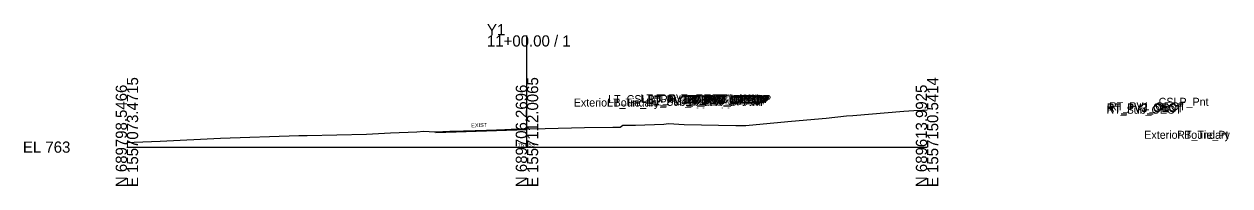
# Model space of a CAD drawing. Extents: x -26 to 303, y -10 to 5005.
# Drawn here: x -25.7 to 275.7, y 990.3 to 1030.7 of the extents above; entities that cross this region are included whole.
import ezdxf

# ---------------------------------------------------------------- set-up
doc = ezdxf.new("R2010")
doc.units = 0
for name, color, linetype in [('Default', 7, 'Continuous'), ('Exist Cross Section Cell', 7, 'Continuous'), ('Exist XS Center Line Elevation Label', 7, 'Continuous'), ('Exist XS Ground Line', 7, 'Continuous'), ('Prop CMT Pvmt Course 1', 7, 'Continuous'), ('Prop CMT Pvmt Surface', 7, 'Continuous'), ('Prop XS SE Text', 7, 'Continuous')]:
    doc.layers.add(name, color=color, linetype=linetype)

msp = doc.modelspace()

# ---------------------------------------------------------------- linework, layer by layer
at = {"layer": 'Exist Cross Section Cell'}
for p, q in [((100, 1000), (100, 1027.94)), ((0, 1000), (100, 1000)), ((100, 1000), (200, 1000))]:
    msp.add_line(p, q, dxfattribs=at)
at = {"layer": 'Exist XS Ground Line'}
msp.add_lwpolyline([(0, 1001.18), (1.79, 1001.23), (8.29, 1001.45), (23.36, 1002.24), (42.94, 1002.87), (44.41, 1002.89), (45.02, 1002.9), (59.93, 1003.22), (65.9, 1003.55), (72.5, 1003.85), (74.21, 1003.98), (76.87, 1003.83), (77.22, 1003.8), (80.71, 1004), (81.25, 1004.02), (92.77, 1004.36), (96.07, 1004.45), (100, 1004.55), (104.53, 1004.67), (114.37, 1004.86), (121.45, 1005.01), (122.06, 1005.01), (123.31, 1005.02), (123.95, 1005.48), (127.14, 1005.51), (134.18, 1005.75), (135.41, 1005.87), (139.33, 1005.62), (152.24, 1005.4), (154.67, 1005.39), (157.29, 1005.67), (166.13, 1006.45), (174.76, 1007.24), (179.85, 1007.83), (181.43, 1007.93), (194.2, 1008.98), (196.68, 1009.17), (198.84, 1009.27), (200, 1009.31)], dxfattribs=at)
at = {"layer": 'Prop CMT Pvmt Course 1'}
for p, q in [((77.22, 1003.68), (100, 1004.42)), ((77.22, 1003.8), (77.22, 1003.68))]:
    msp.add_line(p, q, dxfattribs=at)
for points in [[(100, 1004.55), (100, 1004.42)], [(100, 1004.42), (100, 1004.55)]]:
    msp.add_lwpolyline(points, dxfattribs=at)
at = {"layer": 'Prop CMT Pvmt Surface'}
msp.add_line((77.22, 1003.8), (100, 1004.55), dxfattribs=at)

# ---------------------------------------------------------------- texts
at = {"layer": 'Default'}
for s, height, p in [('LT_CSLP_Pnt', 2, (120.3, 1010.99)), ('LT_CG_Top_BOC', 2, (128.4, 1011.19)), ('LT_PV2_OEOT', 2, (130.29, 1010.94)), ('LT_PV3_OEOT', 2, (130.29, 1010.69)), ('LT_PV1_OEOT', 2, (130.86, 1011.19)), ('RT_PV2_OEEOP', 2, (139.37, 1010.92)), ('RT_PV3_OEEOP', 2, (139.37, 1010.67)), ('LT_PV2_OEEOP', 2, (139.42, 1010.92)), ('LT_PV3_OEEOP', 2, (139.42, 1010.67)), ('RT_PV1_OEEOP', 2, (139.94, 1011.04)), ('LT_PV1_OEEOP', 2, (139.98, 1011.04)), ('RT_PV2_IEEOP', 2, (140.01, 1010.92)), ('LT_PV2_IEEOP', 2, (140.06, 1010.92)), ('RT_PV1_IEEOP', 2, (140.58, 1011.04)), ('LT_PV1_IEEOP', 2, (140.63, 1011.04)), ('RT_PV2_PGL', 2, (141.27, 1010.92)), ('LT_PV2_PGL', 2, (141.32, 1010.92)), ('RT_PV1_PGL', 2, (141.84, 1011.17)), ('LT_PV1_PGL', 2, (141.89, 1011.17)), ('Exterior Boundary', 2, (111.7, 1010.14)), ('LT_Tie_Pt', 2, (120, 1010.14)), ('LT_Sub_OEOT', 2, (130.2, 1010.32)), ('RT_Sub_OEEOP', 2, (139.27, 1010.29)), ('LT_Sub_OEEOP', 2, (139.32, 1010.29)), ('RT_Sub_OEOT', 2, (244.83, 1008.34)), ('RT_PV2_OEOT', 2, (244.93, 1008.96)), ('RT_PV3_OEOT', 2, (244.93, 1008.71)), ('RT_PV1_OEOT', 2, (245.49, 1009.21)), ('CSLP_Pnt', 2, (257.89, 1010.33)), ('Exterior Boundary', 2, (254.3, 1002.07)), ('RT_Tie_Pt', 2, (262.55, 1002.07)), ('-', 0.0001, (0, 1000))]:
    msp.add_text(s, height=height, dxfattribs=at).set_placement(p)
at = {"layer": 'Exist Cross Section Cell'}
for s, p in [('Y1', (90, 1027.94)), ('11+00.00 / 1', (90, 1025.14)), ('EL 763', (-26, 998.6))]:
    msp.add_text(s, height=2.8, dxfattribs=at).set_placement(p)
for s, p in [('E 1557073.4715', (2.8, 990)), ('E 1557112.0065', (102.8, 990)), ('E 1557150.5414', (202.8, 990)), ('N 689798.5466', (0, 990)), ('N 689706.2696', (100, 990)), ('N 689613.9925', (200, 990))]:
    msp.add_text(s, height=2.8, rotation=90, dxfattribs=at).set_placement(p)
at = {"layer": 'Exist XS Center Line Elevation Label'}
msp.add_text('767.55', height=1, dxfattribs=at).set_placement((97.7, 1000.05))
at = {"layer": 'Prop XS SE Text'}
msp.add_text('EXIST', height=1, rotation=1.8768, dxfattribs=at).set_placement((86.07, 1004.93))

doc.saveas('drawing.dxf')
